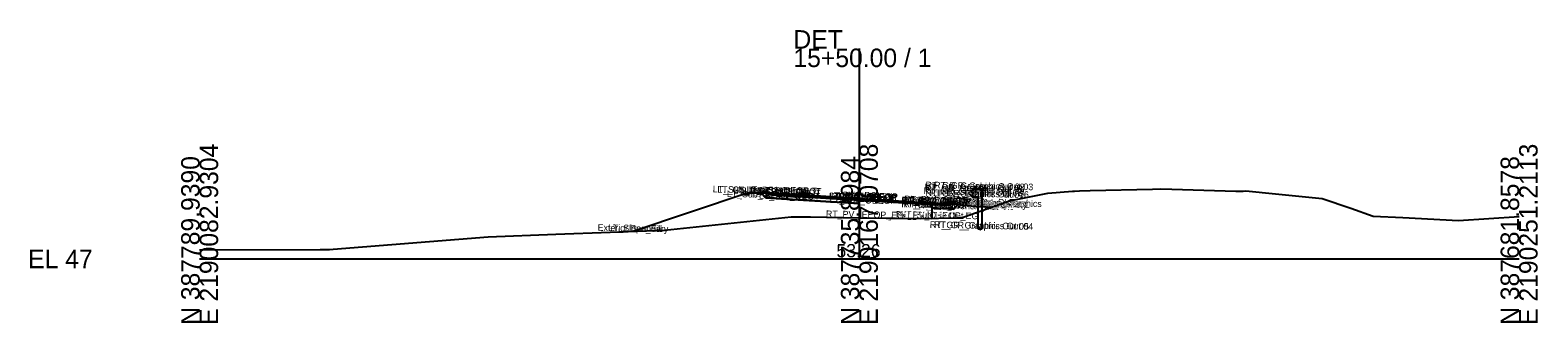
# Model space of a CAD drawing. Extents: x -26 to 1203, y -10 to 9543.
# Drawn here: x -25.7 to 202.8, y 5490.3 to 5534.7 of the extents above; entities that cross this region are included whole.
import ezdxf

# ---------------------------------------------------------------- set-up
doc = ezdxf.new("R2010")
doc.units = 0
for name, color, linetype in [('Default', 7, 'Continuous'), ('Exist CMT Pavement', 7, 'Continuous'), ('Exist Cross Section Cell', 7, 'Continuous'), ('Exist XS Center Line Elevation Label', 7, 'Continuous'), ('Exist XS Ground Line', 7, 'Continuous'), ('Prop CMT Guardrail Graphics', 7, 'Continuous'), ('Prop CMT Pvmt Course 1', 7, 'Continuous'), ('Prop CMT Pvmt Course 1 Wedge', 7, 'Continuous'), ('Prop CMT Pvmt Course 2', 7, 'Continuous'), ('Prop CMT Pvmt Course 2 Wedge', 7, 'Continuous'), ('Prop CMT Pvmt Course 3', 7, 'Continuous'), ('Prop CMT Pvmt Course 3 Wedge', 7, 'Continuous'), ('Prop CMT Pvmt Surface', 7, 'Continuous'), ('Prop CMT Pvmt Surface Shoulder', 7, 'Continuous'), ('Prop CMT Pvmt Wedge Surface 1', 7, 'Continuous'), ('Prop CMT Pvmt Wedge Surface 2', 7, 'Continuous'), ('Prop CMT Pvmt Wedge Surface 3', 7, 'Continuous'), ('Prop CMT Shld Paved Course 1', 7, 'Continuous'), ('Prop CMT Shld Paved Course 2', 7, 'Continuous'), ('Prop CMT Shld Paved Course 3', 7, 'Continuous'), ('Prop CMT Slope Grass', 7, 'Continuous'), ('Prop CMT Subgrade Earthwork', 7, 'Continuous'), ('Scratch_Level_0', 7, 'Continuous')]:
    doc.layers.add(name, color=color, linetype=linetype)

msp = doc.modelspace()

# ---------------------------------------------------------------- linework, layer by layer
at = {"layer": 'Exist CMT Pavement'}
msp.add_lwpolyline([(100, 5506.26), (111, 5506.15)], dxfattribs=at)
at = {"layer": 'Exist Cross Section Cell'}
for p, q in [((100, 5500), (100, 5531.91)), ((0, 5500), (100, 5500)), ((100, 5500), (200, 5500))]:
    msp.add_line(p, q, dxfattribs=at)
at = {"layer": 'Exist XS Ground Line'}
for p, q in [((123.28, 5508.93), (128.55, 5509.99)), ((128.55, 5509.99), (132.29, 5510.29)), ((132.29, 5510.29), (132.63, 5510.31)), ((132.63, 5510.31), (133.37, 5510.34)), ((133.37, 5510.34), (134.96, 5510.4)), ((134.96, 5510.4), (144.43, 5510.61)), ((144.43, 5510.61), (145.66, 5510.64)), ((145.66, 5510.64), (147.38, 5510.59)), ((147.38, 5510.59), (157.05, 5510.31)), ((157.05, 5510.31), (158.19, 5510.31)), ((158.19, 5510.31), (158.58, 5510.32)), ((158.58, 5510.32), (163.09, 5509.86)), ((115.88, 5506.37), (122.91, 5508.85)), ((122.91, 5508.85), (123.28, 5508.93)), ((163.09, 5509.86), (170.16, 5509.16)), ((170.16, 5509.16), (174.47, 5507.69)), ((174.47, 5507.69), (177.87, 5506.5)), ((70.46, 5504.35), (89.67, 5506.38)), ((89.67, 5506.38), (91.89, 5506.39)), ((91.89, 5506.39), (92.61, 5506.38)), ((92.61, 5506.38), (95.04, 5506.34)), ((95.04, 5506.34), (100, 5506.26)), ((100, 5506.26), (109.2, 5506.12)), ((109.2, 5506.12), (114.83, 5506.23)), ((114.83, 5506.23), (115.52, 5506.23)), ((115.52, 5506.23), (115.88, 5506.37)), ((177.87, 5506.5), (182.39, 5506.29)), ((182.39, 5506.29), (190.79, 5505.84)), ((190.79, 5505.84), (200, 5506.44)), ((20.26, 5501.5), (43.75, 5503.35)), ((43.75, 5503.35), (53.98, 5503.77)), ((53.98, 5503.77), (70.46, 5504.35)), ((0, 5501.41), (18.27, 5501.43)), ((18.27, 5501.43), (19.27, 5501.45)), ((19.27, 5501.45), (19.67, 5501.46)), ((19.67, 5501.46), (20.26, 5501.5))]:
    msp.add_line(p, q, dxfattribs=at)
at = {"layer": 'Prop CMT Guardrail Graphics'}
for points in [[(118.61, 5510.58), (117.27, 5510.58), (117, 5510.29)], [(117, 5510.29), (117.27, 5510)], [(117.27, 5510), (117, 5509.71)], [(118.61, 5504.58), (118.61, 5510.58)], [(117, 5509.71), (117.27, 5509.41), (117.94, 5509.41)], [(117.94, 5509.41), (117.94, 5504.58)], [(117.94, 5504.58), (118.61, 5504.58)]]:
    msp.add_lwpolyline(points, dxfattribs=at)
at = {"layer": 'Prop CMT Pvmt Course 1'}
for points in [[(100, 5509.18), (89, 5509.84)], [(89, 5509.84), (89, 5509.59)], [(89, 5509.59), (100, 5508.93)], [(100, 5508.93), (100, 5509.18)], [(100, 5509.18), (111, 5508.52)], [(100, 5508.93), (100, 5509.18)], [(111, 5508.4), (100, 5509.06)], [(100, 5509.06), (100, 5508.93), (100, 5508.93)], [(111, 5508.52), (111, 5508.27), (111, 5508.27), (111, 5508.4)]]:
    msp.add_lwpolyline(points, dxfattribs=at)
msp.add_lwpolyline([(100, 5508.93), (100, 5509.06), (100, 5509.06), (100, 5508.93)], close=True, dxfattribs=at)
at = {"layer": 'Prop CMT Pvmt Course 1 Wedge'}
msp.add_lwpolyline([(100, 5509.06), (111, 5508.4)], dxfattribs=at)
at = {"layer": 'Prop CMT Pvmt Course 2'}
for points in [[(89, 5509.59), (100, 5508.93)], [(100, 5508.93), (89, 5509.59)], [(89, 5509.59), (89, 5509.59)], [(100, 5508.93), (100, 5508.93)], [(111, 5508.27), (111, 5508.27)]]:
    msp.add_lwpolyline(points, dxfattribs=at)
msp.add_lwpolyline([(111, 5508.27), (111, 5508.27), (111, 5508.27)], close=True, dxfattribs=at)
at = {"layer": 'Prop CMT Pvmt Course 2 Wedge'}
msp.add_lwpolyline([(100, 5508.93), (111, 5508.27)], dxfattribs=at)
at = {"layer": 'Prop CMT Pvmt Course 3'}
for points in [[(100, 5508.93), (89, 5509.59)], [(89, 5509.59), (89, 5509.09)], [(89, 5509.09), (100, 5508.43)], [(100, 5508.43), (100, 5508.93)], [(111, 5508.27), (111, 5508.27), (111, 5507.77), (111, 5507.77)], [(111, 5507.77), (111, 5508.27)]]:
    msp.add_lwpolyline(points, dxfattribs=at)
at = {"layer": 'Prop CMT Pvmt Course 3 Wedge'}
msp.add_lwpolyline([(100, 5508.93), (111, 5508.27)], dxfattribs=at)
at = {"layer": 'Prop CMT Pvmt Surface'}
for points in [[(100, 5509.18), (89, 5509.84)], [(100, 5509.18), (111, 5508.52)]]:
    msp.add_lwpolyline(points, dxfattribs=at)
at = {"layer": 'Prop CMT Pvmt Surface Shoulder'}
for points in [[(89, 5509.84), (87, 5509.96)], [(111, 5508.52), (113, 5508.4)]]:
    msp.add_lwpolyline(points, dxfattribs=at)
at = {"layer": 'Prop CMT Pvmt Wedge Surface 1'}
for points in [[(100, 5509.06), (111, 5508.4)], [(111, 5508.27), (111, 5508.52)], [(111, 5508.4), (111, 5508.27), (111, 5508.27)]]:
    msp.add_lwpolyline(points, dxfattribs=at)
at = {"layer": 'Prop CMT Pvmt Wedge Surface 2'}
for points in [[(100, 5508.93), (111, 5508.27)], [(111, 5508.27), (111, 5508.52)]]:
    msp.add_lwpolyline(points, dxfattribs=at)
at = {"layer": 'Prop CMT Pvmt Wedge Surface 3'}
for points in [[(100, 5508.93), (111, 5508.27)], [(111, 5508.27), (111, 5508.52)]]:
    msp.add_lwpolyline(points, dxfattribs=at)
at = {"layer": 'Prop CMT Shld Paved Course 1'}
for points in [[(89, 5509.84), (87, 5509.96), (86.76, 5509.73)], [(86.76, 5509.73), (89, 5509.59)], [(89, 5509.59), (89, 5509.84)], [(111, 5508.52), (113, 5508.4), (113.27, 5508.14)], [(111, 5508.27), (111, 5508.52)], [(113.27, 5508.14), (111, 5508.27)]]:
    msp.add_lwpolyline(points, dxfattribs=at)
at = {"layer": 'Prop CMT Shld Paved Course 2'}
for points in [[(89, 5509.59), (86.76, 5509.73)], [(86.76, 5509.73), (86.76, 5509.73)], [(86.76, 5509.73), (89, 5509.59)], [(89, 5509.59), (89, 5509.59)], [(111, 5508.27), (113.27, 5508.14)], [(113.27, 5508.14), (111, 5508.27)], [(111, 5508.27), (111, 5508.27)], [(113.27, 5508.14), (113.27, 5508.14)]]:
    msp.add_lwpolyline(points, dxfattribs=at)
at = {"layer": 'Prop CMT Shld Paved Course 3'}
for points in [[(89, 5509.59), (86.76, 5509.73), (86.26, 5509.76), (85.79, 5509.28)], [(85.79, 5509.28), (89, 5509.09)], [(89, 5509.09), (89, 5509.59)], [(111, 5508.27), (113.27, 5508.14), (113.77, 5508.11), (114.3, 5507.57)], [(111, 5507.77), (111, 5508.27)], [(114.3, 5507.57), (111, 5507.77)]]:
    msp.add_lwpolyline(points, dxfattribs=at)
at = {"layer": 'Prop CMT Slope Grass'}
for points in [[(87, 5509.96), (83, 5509.96), (65.66, 5504.18)], [(113, 5508.4), (117, 5508.08)], [(117, 5508.08), (120, 5507.84)], [(120, 5507.84), (120.03, 5507.83)]]:
    msp.add_lwpolyline(points, dxfattribs=at)
at = {"layer": 'Prop CMT Subgrade Earthwork'}
for points in [[(85.79, 5509.28), (85.11, 5509.96)], [(89, 5509.09), (85.79, 5509.28)], [(100, 5508.43), (89, 5509.09)], [(111, 5507.77), (111, 5507.77)], [(111, 5507.77), (111, 5506.15)], [(111, 5507.77), (114.3, 5507.57)], [(114.3, 5507.57), (114.97, 5508.24)]]:
    msp.add_lwpolyline(points, dxfattribs=at)

# ---------------------------------------------------------------- texts
at = {"layer": 'Default'}
msp.add_text('-', height=0.0001, dxfattribs=at).set_placement((0, 5500))
at = {"layer": 'Exist Cross Section Cell'}
for s, p in [('DET', (90, 5531.91)), ('15+50.00 / 1', (90, 5529.11)), ('EL 47', (-26, 5498.6))]:
    msp.add_text(s, height=2.8, dxfattribs=at).set_placement(p)
for s, p in [('E 2190082.9304', (2.8, 5490)), ('E 2190167.0708', (102.8, 5490)), ('E 2190251.2113', (202.8, 5490)), ('N 387789.9390', (0, 5490)), ('N 387735.8984', (100, 5490)), ('N 387681.8578', (200, 5490))]:
    msp.add_text(s, height=2.8, rotation=90, dxfattribs=at).set_placement(p)
at = {"layer": 'Exist XS Center Line Elevation Label'}
msp.add_text('53.26', height=2, dxfattribs=at).set_placement((96.52, 5500.26))
at = {"layer": 'Scratch_Level_0'}
for s, p in [('LT_Sub_Trench_Out_DLT', (77.77, 5510.1)), ('LT_GS_OS_CTL', (78.46, 5510.05)), ('LT_Sub_Trench_Out', (79.9, 5509.4)), ('LT_PS3_Shelf_Out', (80.92, 5509.86)), ('LT_PS3_OEOP', (82.55, 5509.81)), ('LT_PS2_OEOP', (82.55, 5509.81)), ('LT_PS1_OEOP', (82.91, 5510.04)), ('LT_PV2_OEOT', (84.75, 5509.67)), ('LT_PV3_OEOT', (84.75, 5509.67)), ('LT_Sub_OEOT', (84.77, 5509.17)), ('LT_PV1_OEOT', (84.87, 5509.92)), ('LT_PV2_OEEOP', (95.39, 5509.02)), ('LT_PV3_OEEOP', (95.39, 5509.02)), ('LT_PV1_OEEOP', (95.51, 5509.14)), ('RT_PV2_IEEOP', (95.71, 5509.01)), ('RT_PV3_IEEOP', (95.71, 5509.01)), ('LT_PV2_IEEOP', (95.77, 5509.01)), ('RT_PV1_IEEOP', (95.83, 5509.14)), ('LT_PV1_IEEOP', (95.89, 5509.14)), ('PV2_PGL', (97.35, 5508.98)), ('PV1_PGL', (97.47, 5509.23)), ('RT_GR_Graphics Out 08', (109.72, 5509.85)), ('RT_GR_Graphics Out 01', (109.89, 5510.43)), ('RT_GR_Graphics Out 07', (109.97, 5509.56)), ('RT_GR_Graphics Out 09', (109.99, 5510.14)), ('RT_GR_Graphics Out 02', (110.02, 5510.72)), ('RT_GR_Graphics Out 06', (110.66, 5509.56)), ('RT_GR_Graphics Out 03', (111.33, 5510.72)), ('LT_Sub_OEEOP', (95.42, 5508.52)), ('RT_PV2_OEEOP', (106.33, 5508.36)), ('RT_PV3_OEEOP', (106.33, 5508.36)), ('RT_Sub_OEEOP', (106.36, 5507.86)), ('RT_PV1_OEEOP', (106.45, 5508.48)), ('RT_PV3_OEOT', (106.69, 5508.36)), ('RT_PV2_OEOT', (106.69, 5508.36)), ('RT_Sub_OEOT', (106.71, 5507.85)), ('RT_PV1_OEOT', (106.81, 5508.6)), ('RT_Sub_Trench_Out_DLT', (107.56, 5508.39)), ('RT_GS_OS_GR_Face_Graphics', (107.94, 5508.26)), ('RT_Sub_Trench_Out', (108.35, 5507.69)), ('RT_PS3_Shelf_Out', (108.37, 5508.21)), ('RT_PS1_OEOP', (108.85, 5508.48)), ('RT_PS3_OEOP', (108.99, 5508.22)), ('RT_PS2_OEOP', (108.99, 5508.22)), ('Exterior Boundary', (114.69, 5507.94)), ('RT_GS_OS_CTL', (115.41, 5507.93)), ('RT_Slope_Cut', (115.97, 5507.91)), ('RT_Slope_Fill', (116.21, 5507.91)), ('RT_PV_IEEOP_EG', (94.92, 5506.36)), ('RT_PV_OEEOP_EG', (105.54, 5506.26)), ('RT_Sub Tie Out', (106.1, 5506.25)), ('RT_GR_Graphics Out 05', (110.66, 5504.72)), ('RT_GR_Graphics Out 04', (111.32, 5504.72)), ('Exterior Boundary', (60.32, 5504.28)), ('LT_Slope_Fill', (61.9, 5504.25))]:
    msp.add_text(s, height=1, rotation=358.8836, dxfattribs=at).set_placement(p)

doc.saveas('drawing.dxf')
